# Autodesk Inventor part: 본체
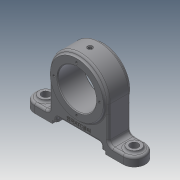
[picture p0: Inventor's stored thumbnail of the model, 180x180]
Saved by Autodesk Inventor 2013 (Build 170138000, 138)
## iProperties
Created: 2019-05
Part Number: 본체
Material: Generic
Document SubType Name: Modeling
Designer: user
Density: 1 g/cm^3
Mass: 168.894 g
Surface Area: 318.799 cm^2
Volume: 168.894 cm^3
Author: user
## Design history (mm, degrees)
sketch "스케치1"
  geometry: C1 r 40 at (0, 0); 1 further point
  constraints: 1 centre point, 1 coincident
  dimensions: "d0" = 80 diameter of C1
extrude "돌출1" new body sketch "스케치1" stored distance "d1" = 30; taper "d2" = 0 deg
sketch "스케치2"
  geometry: C1 r 40 at (0, 0) reference; C2 r 36 at (0, 0)
  constraints: 1 centre point, 1 coincident
  dimensions: "d3" = 72 diameter of C2
extrude "돌출2" join sketch "스케치2" distance "d4" = 3; taper "d5" = 0 deg
sketch "스케치3"
  geometry: C1 r 36 at (0, 0) reference; C2 r 26 at (0, 0)
  constraints: 1 centre point, 1 coincident
  dimensions: "d6" = 52 diameter of C2
extrude "돌출3" cut sketch "스케치3" stored distance "d7" = 3; taper "d8" = 0 deg
node "작업 평면1"
sketch "스케치4"
  geometry: L1 (75, -15)-(-75, -15); L2 (-75, -15)-(-75, 15); L3 (-75, 15)-(75, 15); L4 (75, 15)-(75, -15); L5 (75, -15)-(-75, 15); L6 (-75, -15)-(75, 15); 1 further point
  constraints: 12 end point, 2 midpoint, 2 parallel, 1 horizontal, 1 perpendicular
  dimensions: "d10" = 150 distance of L2.end L3.end; "d11" = 30 distance of L1.end L2.end
extrude "돌출4" join sketch "스케치4" distance "d12" = 12; taper "d13" = 0 deg
sketch "스케치5"
  geometry: L1 (-40, 15)-(40, 15); L2 (40, 15)-(40, -15); L3 (40, -15)-(-40, -15); L4 (-40, -15)-(-40, 15); L5 (-40, 15)-(40, -15); L6 (40, 15)-(-40, -15); 1 further point
  constraints: 12 end point, 2 midpoint, 2 parallel, 1 horizontal, 1 perpendicular
  dimensions: "d14" = 80 distance of L2.end L3.end; "d15" = 30 distance of L1.end L2.end
extrude "돌출5" join sketch "스케치5" stored distance "d16" = 12; taper "d17" = 0 deg
sketch "스케치6"
  geometry: L1 (75, -60)-(-75, -60) reference; L2 (-36, -60)-(36, -60); L3 (36, -60)-(36, -56); L4 (36, -56)-(-36, -56); L5 (-36, -56)-(-36, -60); C1 r 36 at (0, 0) reference; 1 further point
  constraints: 8 end point, 2 parallel, 2 point on line, 1 midpoint, 1 perpendicular, 1 vertical alignment
  dimensions: "d18" = 72 distance of L2.start L2.end; "d19" = 4 distance of L3.end L2.end
extrude "돌출6" cut sketch "스케치6" stored distance "d20" = 12; taper "d21" = 0 deg
sketch "스케치7"
  geometry: L1 (-36, -56)-(36, -56) reference; L2 (-30, -56)-(30, -56); L3 (30, -56)-(30, -50); L4 (30, -50)-(-30, -50); L5 (-30, -50)-(-30, -56); A1 r 40 centre (0, 0) between (40, 0) and (-40, 0) reference; 1 further point
  constraints: 8 end point, 2 parallel, 2 point on line, 1 midpoint, 1 perpendicular, 1 vertical alignment
  dimensions: "d22" = 60 distance of L2.start L2.end; "d23" = 6 distance of L3.end L2.end
extrude "돌출7" cut sketch "스케치7" stored distance "d24" = 12; taper "d25" = 0 deg
sketch "스케치8"
  geometry: L1 (0, 0)-(0, 31); C1 r 36 at (0, 0) reference; 1 further point
  constraints: 2 end point, 1 coincident, 1 vertical
  dimensions: "d26" = 31 distance of L1.start L1.end
hole "구멍1" sketch "스케치8" at (0, 31) diameter "d27" = 3.242; stored, may be unused: countersink angle "d31" = 90 deg, drill point angle "d33" = 118 deg; dims "d28" = 6, "d29" = 4, "d30" = 2, "d32" = 8
sketch "스케치9"
  geometry: C1 r 26 at (0, 0) reference; C2 r 1.5 at (0, 26)
  constraints: 1 centre point, 1 vertical alignment
  dimensions: "d37" = 3 diameter of C2; "d38" = 26 distance of C1.centre C2.centre
extrude "돌출8" cut sketch "스케치9" stored distance "d39" = 12; taper "d40" = 0 deg
node "작업 평면2"
sketch "스케치10"
  geometry: 2 further points
  constraints: 1 coincident
hole "구멍2" sketch "스케치10" at (0, 0) diameter "d42" = 2; stored, may be unused: countersink angle "d46" = 90 deg, drill point angle "d48" = 118 deg; dims "d43" = 6, "d44" = 4, "d45" = 2, "d47" = 8
sketch "스케치11"
  geometry: 3 further points
  constraints: 2 coincident
hole "구멍3" sketch "스케치11" at (0, 0) diameter "d49" = 4.917; stored, may be unused: countersink angle "d53" = 90 deg, drill point angle "d55" = 118 deg; dims "d50" = 8, "d51" = 4, "d52" = 2, "d54" = 10
sketch "스케치12"
  geometry: C1 r 3.5 at (0, 0); 1 further point
  constraints: 1 centre point, 1 coincident
  dimensions: "d56" = 7 diameter of C1
extrude "돌출9" cut sketch "스케치12" distance "d57" = 1; taper "d58" = 0 deg
sketch "스케치13"
  geometry: C1 r 9 at (-60, 0); 1 further point
  constraints: 1 centre point, 1 horizontal alignment
  dimensions: "d59" = 18 diameter of C1; "d60" = 60 distance of C1.centre point (0, 0)
extrude "돌출10" join sketch "스케치13" distance "d61" = 3; taper "d62" = 0 deg
sketch "스케치14"
  geometry: C1 r 9 at (0, 0) reference; C2 r 5.5 at (0, 0); 1 further point
  constraints: 1 centre point, 1 coincident
  dimensions: "d63" = 11 diameter of C2
extrude "돌출11" cut sketch "스케치14" stored distance "d64" = 3; taper "d65" = 0 deg
fillet "모깎기1" dims "d66" = 6
fillet "모깎기2" dims "d67" = 3
fillet "모깎기3" dims "d68" = 3
fillet "모깎기4" dims "d69" = 15
fillet "모깎기5" dims "d70" = 15
fillet "모깎기6" dims "d71" = 3
fillet "모깎기7" dims "d72" = 3
fillet "모깎기8" dims "d73" = 3
sketch "스케치15"
  geometry: L1 (-27, -50)-(27, -50) reference; A1 r 39 centre (0, 0) between (-37, -12.329) and (37, -12.329) reference; 1 further point
  constraints: 1 vertical alignment, 1 other
  dimensions: "d75" = 7 distance from line of L1 point (0, -43)
feature "엠보싱1" sketch "스케치15" dims "d0" = 80, "d76" = 0.5, "d77" = 0
fillet "모깎기9" dims "d78" = 3
chamfer "모따기1" distance "d79" = 1; stored, may be unused: second distance "d80" = 2, angle "d81" = 45 deg
node "솔리드1"
mirror "대칭1"
pattern_circular "원형 패턴1" dims angle "d35" = 360 deg
mirror "대칭2"
mirror "대칭3"
